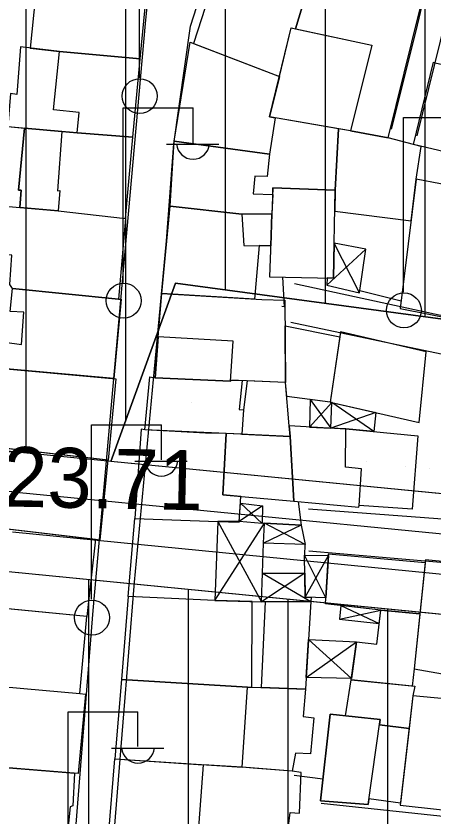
# Model space of a CAD drawing. Extents: x 417997 to 421451, y 4451742 to 4455216.
# Drawn here: x 419514.9 to 419556.9, y 4452473.6 to 4452553.9 of the extents above; entities that cross this region are included whole.
import ezdxf

# ---------------------------------------------------------------- set-up
doc = ezdxf.new("R2010")
doc.units = 0
for name, color, linetype in [('ADA', 7, 'Continuous'), ('ADAKENARI', 7, 'Continuous'), ('B_Mesken', 7, 'Continuous'), ('B_Sundurma', 7, 'Continuous'), ('B_Teras', 7, 'Continuous'), ('Default', 7, 'Continuous'), ('KALDIRIM', 7, 'Continuous'), ('PL_AYA_PARK_DINLENME', 7, 'Continuous'), ('PL_KON_MEV_350', 7, 'Continuous'), ('S_Elektrik_Diregi', 7, 'Continuous'), ('Sinir_Duvar_tek_tarafa_ait', 7, 'Continuous'), ('TR_ORTAYOGUNKONUT', 7, 'Continuous'), ('TR_PARKALANI', 7, 'Continuous'), ('Y_Yol_Kotu', 7, 'Continuous'), ('Yol_Sose', 7, 'Continuous')]:
    doc.layers.add(name, color=color, linetype=linetype)

# ---------------------------------------------------------------- blocks, each defined once
blk = doc.blocks.new('POINT_DISPLAY')
at = {"layer": 'Default'}
blk.add_line((0, 0), (0, 0), dxfattribs=at)

msp = doc.modelspace()

# ---------------------------------------------------------------- linework, layer by layer
at = {"layer": 'ADA'}
for p, q in [((419524.438, 4452509.285), (419530.931, 4452527.141)), ((419524.438, 4452509.285), (419530.931, 4452527.141)), ((419530.931, 4452527.141), (419582.069, 4452520.257)), ((419530.931, 4452527.141), (419582.069, 4452520.257))]:
    msp.add_line(p, q, dxfattribs=at)
at = {"layer": 'ADAKENARI'}
for p, q in [((419524.438, 4452509.285), (419515.336, 4452510.178)), ((419524.438, 4452509.285), (419515.336, 4452510.178)), ((419582.687, 4452503.571), (419524.438, 4452509.285)), ((419582.687, 4452503.571), (419524.438, 4452509.285)), ((419514.164, 4452498.235), (419572.575, 4452492.506)), ((419514.164, 4452498.235), (419572.575, 4452492.506))]:
    msp.add_line(p, q, dxfattribs=at)
msp.add_arc((419511.724, 4452473.355), 37, 84.39749, 131.68944, dxfattribs=at)
msp.add_arc((419511.724, 4452473.355), 37, 84.39749, 131.68944, dxfattribs=at)
at = {"layer": 'B_Mesken'}
for points in [[(419535.869, 4452560.897), (419532.711, 4452551.186), (419541.338, 4452547.878), (419542.511, 4452552.752), (419542.943, 4452552.659), (419544.047, 4452556.32), (419544.564, 4452557.86), (419539.031, 4452559.837)], [(419544.564, 4452557.86), (419544.047, 4452556.32), (419542.943, 4452552.659), (419550.626, 4452551.002), (419548.459, 4452542.424), (419552.254, 4452541.713), (419555.424, 4452554.563), (419556.395, 4452557.617), (419548.379, 4452559.471), (419545.341, 4452560.174)], [(419527.383, 4452549.635), (419527.877, 4452554.785), (419518.189, 4452558.109), (419518.215, 4452559.108), (419515.559, 4452559.616), (419515.229, 4452556.1), (419516.887, 4452555.98), (419516.328, 4452550.722), (419519.27, 4452550.389)], [(419540.364, 4452543.828), (419542.511, 4452552.752), (419550.626, 4452551.002), (419548.459, 4452542.424)], [(419530.784, 4452541.389), (419532.391, 4452551.308), (419541.338, 4452547.878), (419540.364, 4452543.828), (419540.934, 4452543.729), (419540.335, 4452540.098)], [(419526.655, 4452541.789), (419527.383, 4452549.635), (419519.27, 4452550.389), (419515.355, 4452550.832), (419515, 4452546.083), (419514.366, 4452546.153), (419514.106, 4452542.852), (419515.768, 4452542.7), (419519.526, 4452542.357), (419521.054, 4452542.217)], [(419567.38, 4452546.884), (419565.66, 4452538.066), (419563.459, 4452538.516), (419563.54, 4452538.995), (419554.786, 4452541.038), (419556.789, 4452549.306), (419556.97, 4452549.253)], [(419546.948, 4452536.461), (419547.283, 4452542.628), (419540.934, 4452543.729), (419540.335, 4452540.098), (419540.104, 4452537.841), (419538.88, 4452537.891), (419538.712, 4452536.112), (419540.67, 4452536.047), (419540.695, 4452536.712)], [(419519.137, 4452534.396), (419525.903, 4452533.648), (419526.655, 4452541.789), (419521.054, 4452542.217), (419519.526, 4452542.357), (419515.768, 4452542.7), (419515.183, 4452536.491), (419515.432, 4452536.49), (419515.313, 4452534.749)], [(419546.948, 4452536.461), (419546.907, 4452534.383), (419554.555, 4452533.413), (419555.071, 4452537.595), (419555.577, 4452540.854), (419554.786, 4452541.038), (419552.254, 4452541.713), (419548.459, 4452542.424), (419547.283, 4452542.628)], [(419530.378, 4452534.86), (419530.784, 4452541.389), (419540.335, 4452540.098), (419540.104, 4452537.841), (419538.88, 4452537.891), (419538.712, 4452536.112), (419540.67, 4452536.047), (419540.596, 4452534.105), (419537.559, 4452534.057)], [(419555.071, 4452537.595), (419553.468, 4452524.598), (419561.74, 4452522.971), (419562.383, 4452536.191)], [(419540.695, 4452536.712), (419540.358, 4452527.78), (419546.775, 4452527.658), (419546.948, 4452536.461)], [(419525.903, 4452533.648), (419525.196, 4452525.538), (419514.563, 4452526.618), (419514.292, 4452527.004), (419514.506, 4452529.972), (419513.236, 4452529.999), (419513.434, 4452534.893), (419515.313, 4452534.749), (419519.137, 4452534.396)], [(419530.378, 4452534.86), (419537.559, 4452534.057), (419540.596, 4452534.105), (419540.476, 4452530.906), (419539.303, 4452530.921), (419538.835, 4452525.542), (419529.543, 4452526.112)], [(419525.196, 4452525.538), (419525.468, 4452525.537), (419524.725, 4452517.583), (419512.047, 4452518.739), (419512.326, 4452521.429), (419515.477, 4452521.01), (419515.715, 4452524.249), (419514.332, 4452524.322), (419514.563, 4452526.618)], [(419529.189, 4452521.758), (419529.543, 4452526.112), (419539.578, 4452525.496), (419541.889, 4452525.45), (419541.969, 4452517.178), (419536.457, 4452517.438), (419536.449, 4452517.319), (419528.876, 4452517.645)], [(419541.914, 4452522.879), (419547.398, 4452521.763), (419546.446, 4452515.222), (419542.086, 4452515.784), (419541.969, 4452517.178)], [(419546.446, 4452515.222), (419555.371, 4452513.189), (419556.056, 4452520.25), (419547.471, 4452522.261)], [(419512.654, 4452510.71), (419513.328, 4452515.976), (419511.835, 4452516.14), (419512.047, 4452518.739), (419524.942, 4452517.563), (419524.165, 4452509.391)], [(419527.851, 4452512.456), (419528.349, 4452517.748), (419528.876, 4452517.645), (419536.449, 4452517.319), (419536.457, 4452517.438), (419537.619, 4452517.383), (419537.309, 4452514.468), (419537.729, 4452514.446), (419537.561, 4452512.006), (419535.994, 4452512.08), (419533.936, 4452512.108)], [(419542.333, 4452512.834), (419541.969, 4452517.178), (419538.122, 4452517.359), (419537.729, 4452514.446), (419537.561, 4452512.006), (419542.43, 4452511.777)], [(419535.994, 4452512.08), (419527.851, 4452512.456), (419527.48, 4452512.517), (419526.842, 4452503.561), (419535.166, 4452503.242), (419537.294, 4452503.175), (419537.478, 4452505.769), (419535.654, 4452505.929)], [(419542.788, 4452505.304), (419549.303, 4452504.701), (419549.344, 4452504.841), (419549.576, 4452508.535), (419547.957, 4452508.701), (419548.009, 4452512.513), (419542.333, 4452512.834), (419542.43, 4452511.777)], [(419548.01, 4452512.555), (419555.224, 4452511.83), (419554.66, 4452504.482), (419549.344, 4452504.841), (419549.576, 4452508.535), (419547.957, 4452508.701)], [(419535.994, 4452512.08), (419535.654, 4452505.929), (419542.788, 4452505.304), (419542.43, 4452511.777)], [(419510.317, 4452502.943), (419523.36, 4452501.419), (419524.165, 4452509.391), (419511.041, 4452510.895)], [(419526.842, 4452503.561), (419535.166, 4452503.242), (419534.877, 4452495.325), (419526.181, 4452495.73)], [(419522.878, 4452501.476), (419522.038, 4452493.729), (419512.667, 4452494.639), (419513.135, 4452499.009), (419510.253, 4452499.385), (419510.36, 4452500.397), (419510.648, 4452502.904)], [(419551.503, 4452494.363), (419545.976, 4452495.004), (419546.273, 4452500.027), (419555.953, 4452499.127), (419555.431, 4452493.984)], [(419555.983, 4452499.424), (419554.871, 4452488.466), (419560.543, 4452487.47), (419560.788, 4452489.041), (419563.116, 4452488.614), (419564.165, 4452498.598)], [(419526.181, 4452495.73), (419525.507, 4452487.41), (419538.142, 4452486.625), (419538.569, 4452486.643), (419538.615, 4452495.235), (419534.877, 4452495.325)], [(419509.685, 4452487.055), (419521.334, 4452485.996), (419522.038, 4452493.729), (419510.31, 4452494.868)], [(419539.551, 4452486.605), (419539.957, 4452495.207), (419544.493, 4452495.229), (419543.967, 4452486.434)], [(419548.555, 4452487.368), (419549.068, 4452491.19), (419551.131, 4452490.962), (419551.503, 4452494.363), (419555.431, 4452493.984), (419554.871, 4452488.466), (419554.662, 4452486.752)], [(419521.334, 4452485.996), (419521.877, 4452485.949), (419521.149, 4452477.991), (419510.854, 4452478.82), (419511.069, 4452482.37), (419508.849, 4452482.598), (419508.974, 4452484.401), (419509.209, 4452487.069), (419509.685, 4452487.055)], [(419524.842, 4452479.453), (419537.597, 4452478.608), (419538.142, 4452486.625), (419525.507, 4452487.41)], [(419547.964, 4452483.78), (419548.555, 4452487.368), (419554.922, 4452486.726), (419554.744, 4452485.777), (419554.359, 4452482.508), (419551.373, 4452482.851), (419551.452, 4452483.406)], [(419538.569, 4452486.643), (419543.967, 4452486.434), (419543.727, 4452483.7), (419544.789, 4452483.573), (419544.478, 4452479.963), (419542.962, 4452480.019), (419542.64, 4452478.232), (419537.597, 4452478.608), (419538.142, 4452486.625)], [(419561.565, 4452477.319), (419562.664, 4452484.594), (419559.322, 4452485.024), (419559.362, 4452485.322), (419554.744, 4452485.777), (419553.453, 4452474.799), (419561.336, 4452473.934)], [(419553.477, 4452475.006), (419550.324, 4452475.429), (419550.247, 4452474.88), (419545.46, 4452475.257), (419546.447, 4452483.942), (419551.452, 4452483.406), (419551.373, 4452482.851), (419554.359, 4452482.508)], [(419533.705, 4452478.866), (419533.103, 4452470.801), (419524.392, 4452471.727), (419524.192, 4452471.707), (419524.842, 4452479.453)], [(419520.78, 4452478.02), (419520.634, 4452474.742), (419520.362, 4452474.652), (419519.896, 4452470.004), (419508.848, 4452470.815), (419507.864, 4452470.941), (419508.239, 4452475.683), (419509.596, 4452475.542), (419509.857, 4452478.934), (419510.854, 4452478.82)], [(419537.597, 4452478.608), (419533.705, 4452478.866), (419533.103, 4452470.801), (419535.297, 4452470.568), (419541.921, 4452469.962), (419542.428, 4452474.078), (419543.36, 4452474.007), (419543.52, 4452478.077), (419542.64, 4452478.232), (419538.72, 4452478.524)]]:
    msp.add_lwpolyline(points, close=True, dxfattribs=at)
at = {"layer": 'B_Sundurma'}
for p, q in [((419549.39, 4452526.194), (419546.844, 4452531.152)), ((419546.093, 4452526.951), (419550.01, 4452530.558)), ((419544.378, 4452512.718), (419546.612, 4452515.184)), ((419544.429, 4452515.482), (419546.519, 4452512.598)), ((419550.813, 4452512.274), (419546.612, 4452515.184)), ((419551.022, 4452514.179), (419546.519, 4452512.598)), ((419539.633, 4452504.823), (419537.301, 4452503.267)), ((419537.429, 4452505.078), (419539.598, 4452503.042)), ((419534.877, 4452495.325), (419539.839, 4452503.073)), ((419535.166, 4452503.242), (419539.545, 4452495.212)), ((419543.513, 4452502.898), (419539.764, 4452501.079)), ((419543.927, 4452500.934), (419539.839, 4452503.073)), ((419546.01, 4452495.592), (419543.86, 4452499.885)), ((419543.926, 4452495.679), (419546.262, 4452499.851)), ((419543.888, 4452498.07), (419539.545, 4452495.212)), ((419539.652, 4452498.083), (419544.493, 4452495.229)), ((419547.511, 4452494.826), (419551.356, 4452493.019)), ((419547.386, 4452493.465), (419551.503, 4452494.363)), ((419544.038, 4452487.609), (419549.068, 4452491.19)), ((419548.574, 4452487.514), (419544.265, 4452491.413))]:
    msp.add_line(p, q, dxfattribs=at)
for points in [[(419546.775, 4452527.658), (419546.134, 4452527.67), (419546.093, 4452526.951), (419549.39, 4452526.194), (419550.01, 4452530.558), (419546.844, 4452531.152)], [(419544.429, 4452515.482), (419544.378, 4452512.718), (419546.519, 4452512.598), (419546.612, 4452515.184), (419546.446, 4452515.222)], [(419551.022, 4452514.179), (419550.813, 4452512.274), (419548.01, 4452512.555), (419546.519, 4452512.598), (419546.612, 4452515.184)], [(419537.429, 4452505.078), (419539.633, 4452504.823), (419539.598, 4452503.042), (419537.301, 4452503.267)], [(419535.166, 4452503.242), (419534.877, 4452495.325), (419539.545, 4452495.212), (419539.652, 4452498.083), (419539.764, 4452501.079), (419539.839, 4452503.073), (419539.598, 4452503.042), (419537.301, 4452503.267)], [(419543.513, 4452502.898), (419543.927, 4452500.934), (419539.764, 4452501.079), (419539.839, 4452503.073)], [(419546.01, 4452495.592), (419543.926, 4452495.679), (419543.86, 4452499.885), (419546.262, 4452499.851)], [(419539.652, 4452498.083), (419543.888, 4452498.07), (419543.926, 4452495.679), (419544.514, 4452495.655), (419544.493, 4452495.229), (419540.127, 4452495.205), (419539.545, 4452495.212)], [(419547.511, 4452494.826), (419547.386, 4452493.465), (419551.356, 4452493.019), (419551.503, 4452494.363)], [(419548.574, 4452487.514), (419544.038, 4452487.609), (419544.265, 4452491.413), (419549.068, 4452491.19)]]:
    msp.add_lwpolyline(points, close=True, dxfattribs=at)
at = {"layer": 'B_Teras'}
for points in [[(419514.106, 4452542.852), (419521.054, 4452542.217), (419521.242, 4452544.275), (419518.685, 4452544.532), (419519.27, 4452550.389), (419515.355, 4452550.832), (419515, 4452546.083), (419514.366, 4452546.153)], [(419519.526, 4452542.357), (419519.076, 4452536.409), (419519.325, 4452536.431), (419519.137, 4452534.396), (419515.313, 4452534.749), (419515.432, 4452536.49), (419515.183, 4452536.491), (419515.768, 4452542.7)], [(419540.596, 4452534.105), (419537.559, 4452534.057), (419537.791, 4452530.94), (419540.476, 4452530.906)], [(419528.876, 4452517.645), (419536.449, 4452517.319), (419536.703, 4452521.332), (419529.189, 4452521.758)], [(419546.447, 4452483.942), (419545.46, 4452475.257), (419550.247, 4452474.88), (419551.452, 4452483.406)]]:
    msp.add_lwpolyline(points, close=True, dxfattribs=at)
at = {"layer": 'KALDIRIM'}
for p, q in [((419514.945, 4452506.197), (419585.057, 4452499.32)), ((419514.945, 4452506.197), (419585.057, 4452499.32)), ((419514.555, 4452502.216), (419584.914, 4452495.314)), ((419514.555, 4452502.216), (419584.914, 4452495.314))]:
    msp.add_line(p, q, dxfattribs=at)
msp.add_arc((419511.724, 4452473.355), 33, 84.39749, 131.68944, dxfattribs=at)
msp.add_arc((419511.724, 4452473.355), 33, 84.39749, 131.68944, dxfattribs=at)
at = {"layer": 'PL_AYA_PARK_DINLENME'}
msp.add_lwpolyline([(419582.069, 4452520.257), (419582.687, 4452503.571), (419524.438, 4452509.285), (419530.931, 4452527.141)], close=True, dxfattribs=at)
msp.add_lwpolyline([(419582.069, 4452520.257), (419582.687, 4452503.571), (419524.438, 4452509.285), (419530.931, 4452527.141)], close=True, dxfattribs=at)
at = {"layer": 'PL_KON_MEV_350'}
for points in [[(419623.77, 4452499.541), (419582.687, 4452503.571), (419582.069, 4452520.257), (419530.931, 4452527.141), (419524.438, 4452509.285), (419515.336, 4452510.178), (419511.524, 4452510.354), (419507.714, 4452510.137), (419503.948, 4452509.528), (419500.263, 4452508.535), (419496.701, 4452507.168), (419493.298, 4452505.441), (419490.092, 4452503.373), (419487.115, 4452500.985), (419468.114, 4452484.062), (419466.085, 4452482.436), (419463.898, 4452481.029), (419461.577, 4452479.858)], [(419462.822, 4452467.51), (419466.42, 4452468.878), (419469.855, 4452470.612), (419473.092, 4452472.694), (419476.095, 4452475.101), (419495.096, 4452492.024), (419497.107, 4452493.637), (419499.274, 4452495.035), (419501.573, 4452496.201), (419503.98, 4452497.125), (419506.469, 4452497.797), (419509.015, 4452498.208), (419511.589, 4452498.354), (419514.164, 4452498.235), (419572.575, 4452492.506), (419567.658, 4452443.954), (419562.661, 4452394.609)]]:
    msp.add_lwpolyline(points, dxfattribs=at)
at = {"layer": 'S_Elektrik_Diregi'}
for p, q in [((419527.296, 4452547.739), (419527.296, 4452565.239)), ((419525.679, 4452527.226), (419525.679, 4452544.726)), ((419525.679, 4452544.726), (419532.679, 4452544.726)), ((419532.679, 4452541.226), (419532.679, 4452544.726)), ((419553.795, 4452526.256), (419553.795, 4452543.756)), ((419553.795, 4452543.756), (419560.795, 4452543.756)), ((419530.019, 4452541.086), (419535.269, 4452541.086)), ((419522.501, 4452495.452), (419522.501, 4452512.952)), ((419522.501, 4452512.952), (419529.501, 4452512.952)), ((419529.501, 4452509.452), (419529.501, 4452512.952)), ((419526.841, 4452509.312), (419532.091, 4452509.312)), ((419520.157, 4452466.679), (419520.157, 4452484.179)), ((419520.157, 4452484.179), (419527.157, 4452484.179)), ((419527.157, 4452480.679), (419527.157, 4452484.179)), ((419524.497, 4452480.539), (419529.747, 4452480.539))]:
    msp.add_line(p, q, dxfattribs=at)
for centre in [(419527.332, 4452545.904), (419525.715, 4452525.391), (419553.831, 4452524.421), (419522.537, 4452493.616)]:
    msp.add_circle(centre, 1.75, dxfattribs=at)
for centre in [(419532.68, 4452541.239), (419529.502, 4452509.465), (419527.158, 4452480.692)]:
    msp.add_arc(centre, 1.658, 184.83843, 355.14641, dxfattribs=at)
at = {"layer": 'Sinir_Duvar_tek_tarafa_ait'}
for points in [[(419541.664, 4452527.755), (419541.818, 4452524.784), (419541.575, 4452524.81)], [(419553.56, 4452525.341), (419549.416, 4452526.382)], [(419543.24, 4452505.262), (419543.513, 4452502.898), (419539.839, 4452503.073)], [(419543.886, 4452500.935), (419543.86, 4452499.885)], [(419545.707, 4452477.429), (419542.819, 4452477.768)]]:
    msp.add_lwpolyline(points, dxfattribs=at)
at = {"layer": 'TR_ORTAYOGUNKONUT'}
for p, q in [((419555.951, 4452523.773), (419555.951, 4452598.801)), ((419555.951, 4452523.773), (419555.951, 4452598.801)), ((419545.951, 4452525.119), (419545.951, 4452596.207)), ((419545.951, 4452525.119), (419545.951, 4452596.207)), ((419535.951, 4452526.466), (419535.951, 4452593.612)), ((419535.951, 4452526.466), (419535.951, 4452593.612)), ((419525.951, 4452513.446), (419525.951, 4452591.018)), ((419525.951, 4452513.446), (419525.951, 4452591.018)), ((419515.951, 4452510.118), (419515.951, 4452588.424)), ((419515.951, 4452510.118), (419515.951, 4452588.424)), ((419522.22, 4452462.733), (419522.22, 4452497.445)), ((419522.22, 4452462.733), (419522.22, 4452497.445)), ((419532.22, 4452398.919), (419532.22, 4452496.464)), ((419532.22, 4452398.919), (419532.22, 4452496.464)), ((419542.22, 4452397.503), (419542.22, 4452495.483)), ((419542.22, 4452397.503), (419542.22, 4452495.483)), ((419552.22, 4452396.087), (419552.22, 4452494.502)), ((419552.22, 4452396.087), (419552.22, 4452494.502))]:
    msp.add_line(p, q, dxfattribs=at)
at = {"layer": 'Yol_Sose'}
for points in [[(419539.99, 4452426.405), (419522.024, 4452433.508), (419521.764, 4452433.71), (419521.685, 4452434.091), (419523.399, 4452455.043), (419526.809, 4452497.186), (419530.016, 4452531.407), (419530.751, 4452541.136), (419532.417, 4452552.929), (419536.252, 4452564.794), (419545.328, 4452588.6), (419549.54, 4452599.199), (419549.862, 4452599.539), (419550.244, 4452599.658), (419565.143, 4452598.802), (419565.283, 4452598.681), (419565.503, 4452598.459), (419565.582, 4452598.078), (419559.041, 4452569.467), (419555.028, 4452552.446), (419552.545, 4452542.582)], [(419528.036, 4452554.843), (419527.871, 4452553.181), (419522.637, 4452494.342), (419518.926, 4452447.707), (419517.705, 4452436.869), (419517.361, 4452436.323), (419516.448, 4452436.03), (419492.746, 4452438.405), (419492.428, 4452438.633), (419492.11, 4452439.067), (419492.021, 4452439.682), (419494.07, 4452460.21), (419494.237, 4452462.019), (419499.017, 4452517.864), (419503.321, 4452566.529)], [(419555.176, 4452541.922), (419560.981, 4452565.569), (419561.061, 4452565.649), (419561.243, 4452565.769), (419561.343, 4452565.828), (419585.153, 4452559.985), (419585.314, 4452559.884), (419585.614, 4452559.562), (419585.793, 4452558.999), (419583.139, 4452540.319), (419582.501, 4452535.664), (419582.392, 4452533.035), (419582.549, 4452520.087), (419582.307, 4452519.646), (419582.105, 4452519.366), (419581.522, 4452519.308), (419564.153, 4452522.459), (419542.85, 4452527.09)], [(419542.476, 4452523.237), (419574.573, 4452516.501), (419574.894, 4452516.319), (419575.094, 4452515.938), (419575.052, 4452515.476), (419573.063, 4452503.164), (419572.962, 4452502.984), (419572.72, 4452502.664), (419572.016, 4452502.425), (419544.248, 4452504.49)], [(419544.295, 4452500.317), (419572.282, 4452497.91), (419573.025, 4452497.767), (419573.285, 4452497.465), (419573.284, 4452497.264), (419570.673, 4452472.756), (419570.531, 4452472.455), (419570.269, 4452472.336), (419545.516, 4452474.992)]]:
    msp.add_lwpolyline(points, dxfattribs=at)

# ---------------------------------------------------------------- block references
at = {"layer": 'TR_PARKALANI', "xscale": 0.1, "yscale": 0.10000000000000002}
for p in [(419547.321, 4452517.761), (419547.321, 4452517.761), (419532.549, 4452515.156), (419532.549, 4452515.156), (419550.091, 4452509.25), (419550.091, 4452509.25), (419553.982, 4452508.781), (419553.982, 4452508.781), (419556.377, 4452508.59), (419556.377, 4452508.59)]:
    msp.add_blockref('POINT_DISPLAY', p, dxfattribs=at)

# ---------------------------------------------------------------- texts
at = {"layer": 'Y_Yol_Kotu'}
msp.add_text('123.71 ', height=6, rotation=358.87031, dxfattribs=at).set_placement((419509.093, 4452504.854))

doc.saveas('drawing.dxf')
